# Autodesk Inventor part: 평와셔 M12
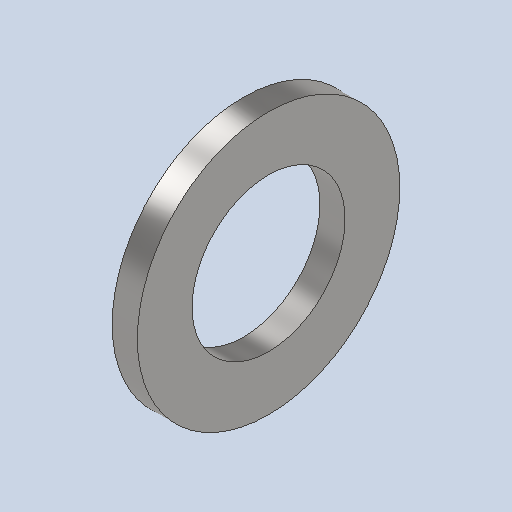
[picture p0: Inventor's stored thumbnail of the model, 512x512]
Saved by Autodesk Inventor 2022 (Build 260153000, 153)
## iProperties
Created: 2024-07
Part Number: 평와셔 M12
Material: 강철, 연강
Description: 평면 와셔
Document SubType Name: Modeling
Designer: PC-01
Density: 7.85 g/cm^3
Appearance: 기본값
Author: jhkim
Sending System: Autodesk Inventor 2025
Preprocessor: ST-DEVELOPER v20
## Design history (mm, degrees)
feature "Solid1"
node "솔리드1"
